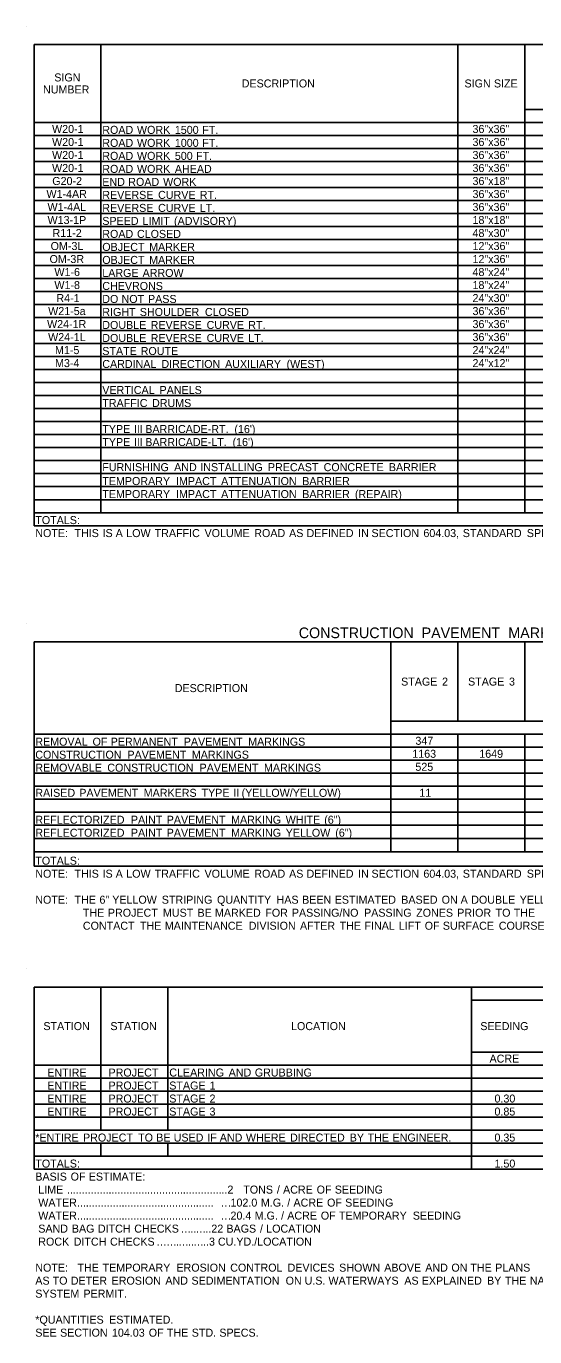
# Model space of a CAD drawing. Extents: x 120 to 5602, y 34 to 1048.
# Drawn here: x 120 to 501, y 66 to 1048 of the extents above; entities that cross this region are included whole.
import ezdxf

# ---------------------------------------------------------------- set-up
doc = ezdxf.new("R2010")
doc.units = 0
doc.layers.add('Default', color=7, linetype='Continuous')
doc.layers.add('STAMP', color=7, linetype='Continuous')

msp = doc.modelspace()

# ---------------------------------------------------------------- linework, layer by layer
at = {"layer": 'Default'}
for p, q in [((125.72, 1034.81), (1233.32, 1034.81)), ((125.72, 674.06), (125.72, 1034.81)), ((125.72, 674.06), (125.72, 1034.81)), ((175.93, 683.81), (175.93, 1034.81)), ((443.57, 683.81), (443.57, 1034.81)), ((493.78, 683.81), (493.78, 1034.81)), ((493.78, 986.06), (644.42, 986.06)), ((125.72, 976.31), (1233.32, 976.31)), ((175.93, 722.81), (175.93, 976.31)), ((443.57, 683.81), (443.57, 976.31)), ((493.78, 683.81), (493.78, 976.31)), ((125.72, 966.56), (1233.32, 966.56)), ((125.72, 956.81), (1233.32, 956.81)), ((125.72, 947.06), (1233.32, 947.06)), ((125.72, 937.31), (1233.32, 937.31)), ((125.72, 927.56), (1233.32, 927.56)), ((125.72, 917.81), (1233.32, 917.81)), ((125.72, 908.06), (1233.32, 908.06)), ((125.72, 898.31), (1233.32, 898.31)), ((125.72, 888.56), (1233.32, 888.56)), ((125.72, 878.81), (1233.32, 878.81)), ((125.72, 869.06), (1233.32, 869.06)), ((125.72, 859.31), (1233.32, 859.31)), ((125.72, 849.56), (1233.32, 849.56)), ((125.72, 839.81), (1233.32, 839.81)), ((125.72, 830.06), (1233.32, 830.06)), ((125.72, 820.31), (1233.32, 820.31)), ((125.72, 810.56), (1233.32, 810.56)), ((125.72, 800.81), (1233.32, 800.81)), ((125.72, 791.06), (1233.32, 791.06)), ((125.72, 781.31), (1233.32, 781.31)), ((125.72, 771.56), (1233.32, 771.56)), ((125.72, 761.81), (1233.32, 761.81)), ((125.72, 752.06), (1233.32, 752.06)), ((125.72, 742.31), (1233.32, 742.31)), ((125.72, 732.56), (1233.32, 732.56)), ((125.72, 722.81), (1233.32, 722.81)), ((125.72, 713.06), (175.93, 713.06)), ((175.93, 713.06), (702.43, 713.06)), ((175.93, 683.81), (175.93, 713.06)), ((125.72, 703.31), (1233.32, 703.31)), ((125.72, 693.56), (1233.32, 693.56)), ((125.72, 683.81), (1233.32, 683.81)), ((125.72, 674.06), (1233.32, 674.06)), ((125.72, 586.92), (969.09, 586.92)), ((125.72, 418.74), (125.72, 586.92)), ((125.72, 418.74), (125.72, 586.92)), ((393.36, 429.46), (393.36, 586.92)), ((443.57, 527.45), (443.57, 586.92)), ((493.78, 527.45), (493.78, 586.92)), ((393.36, 527.45), (969.09, 527.45)), ((393.36, 429.46), (393.36, 527.45)), ((125.72, 517.7), (969.09, 517.7)), ((443.57, 429.46), (443.57, 517.7)), ((443.57, 429.46), (443.57, 517.7)), ((493.78, 429.46), (493.78, 517.7)), ((493.78, 429.46), (493.78, 517.7)), ((125.72, 507.95), (969.09, 507.95)), ((125.72, 498.2), (969.09, 498.2)), ((125.72, 488.45), (969.09, 488.45)), ((125.72, 478.7), (969.09, 478.7)), ((125.72, 468.95), (969.09, 468.95)), ((125.72, 459.2), (969.09, 459.2)), ((125.72, 449.45), (969.09, 449.45)), ((125.72, 439.7), (969.09, 439.7)), ((125.72, 429.46), (969.09, 429.46)), ((125.72, 418.74), (969.09, 418.74)), ((125.72, 328.2), (1244.53, 328.2)), ((125.72, 191.7), (125.72, 328.2)), ((125.72, 191.7), (125.72, 328.2)), ((175.93, 220.95), (175.93, 328.2)), ((226.14, 220.95), (226.14, 328.2)), ((453.81, 191.7), (453.81, 328.2)), ((453.81, 318.45), (1244.53, 318.45)), ((453.81, 279.45), (1118.27, 279.45)), ((125.72, 269.7), (1244.53, 269.7)), ((175.93, 220.95), (175.93, 269.7)), ((226.14, 220.95), (226.14, 269.7)), ((453.81, 220.95), (453.81, 269.7)), ((125.72, 259.95), (1244.53, 259.95)), ((125.72, 250.2), (1244.53, 250.2)), ((125.72, 240.45), (1244.53, 240.45)), ((125.72, 230.7), (1244.53, 230.7)), ((125.72, 220.95), (1244.53, 220.95)), ((125.72, 211.2), (1244.53, 211.2)), ((175.93, 201.45), (175.93, 211.2)), ((175.93, 201.45), (175.93, 211.2)), ((226.14, 201.45), (226.14, 211.2)), ((226.14, 201.45), (226.14, 211.2)), ((453.81, 191.7), (453.81, 211.2)), ((125.72, 201.45), (718.52, 201.45)), ((125.72, 191.7), (1244.53, 191.7))]:
    msp.add_line(p, q, dxfattribs=at)
at = {"layer": 'STAMP'}
for p, q in [((119.87, 1048.46), (119.87, 1048.46)), ((119.87, 600.57), (119.87, 600.57)), ((119.87, 341.85), (119.87, 341.85))]:
    msp.add_line(p, q, dxfattribs=at)

# ---------------------------------------------------------------- texts
at = {"layer": 'Default'}
for s, height, p in [('SIGN', 6, (140.91, 1007.06)), ('NUMBER', 6, (132.45, 998.06)), ('DESCRIPTION', 6, (281.44, 1002.56)), ('SIGN', 6, (448.49, 1002.56)), (' SIZE', 6, (468.31, 1002.56)), ('W20-1', 6, (139.25, 968.43)), ('ROAD', 6, (176.91, 967.76)), (' WORK', 6, (200.68, 967.76)), (' 1500', 6, (229.07, 967.76)), (' FT.', 6, (249.64, 967.76)), ('36"x36"', 6, (454.48, 968.43)), ('W20-1', 6, (139.25, 958.68)), ('ROAD', 6, (176.91, 958.01)), (' WORK', 6, (200.68, 958.01)), (' 1000', 6, (229.07, 958.01)), (' FT.', 6, (249.64, 958.01)), ('36"x36"', 6, (454.48, 958.68)), ('W20-1', 6, (139.25, 948.93)), ('ROAD', 6, (176.91, 948.26)), (' WORK', 6, (200.68, 948.26)), (' 500', 6, (229.07, 948.26)), (' FT.', 6, (244.98, 948.26)), ('36"x36"', 6, (454.48, 948.93)), ('W20-1', 6, (139.25, 939.18)), ('ROAD', 6, (176.91, 938.51)), (' WORK', 6, (200.68, 938.51)), (' AHEAD', 6, (229.07, 938.51)), ('36"x36"', 6, (454.48, 939.18)), ('G20-2', 6, (139.4, 929.43)), ('END', 6, (176.91, 928.76)), (' ROAD', 6, (194.16, 928.76)), (' WORK', 6, (220.26, 928.76)), ('36"x18"', 6, (454.48, 929.43)), ('W1-4AR', 6, (135.05, 919.68)), ('REVERSE', 6, (176.91, 919.01)), (' CURVE', 6, (216.53, 919.01)), (' RT.', 6, (247.76, 919.01)), ('36"x36"', 6, (454.48, 919.68)), ('W1-4AL', 6, (135.84, 909.93)), ('REVERSE', 6, (176.91, 909.26)), (' CURVE', 6, (216.53, 909.26)), (' LT.', 6, (247.76, 909.26)), ('36"x36"', 6, (454.48, 909.93)), ('W13-1P', 6, (135.87, 900.18)), ('SPEED', 6, (176.91, 899.51)), (' LIMIT', 6, (204.88, 899.51)), (' (ADVISORY)', 6, (228.46, 899.51)), ('18"x18"', 6, (454.48, 900.18)), ('R11-2', 6, (139.63, 890.43)), ('ROAD', 6, (176.91, 889.76)), (' CLOSED', 6, (200.68, 889.76)), ('48"x30"', 6, (454.48, 890.43)), ('OM-3L', 6, (138.17, 880.68)), ('OBJECT', 6, (176.91, 880.01)), (' MARKER', 6, (209.81, 880.01)), ('12"x36"', 6, (454.48, 880.68)), ('OM-3R', 6, (137.38, 870.93)), ('OBJECT', 6, (176.91, 870.26)), (' MARKER', 6, (209.81, 870.26)), ('12"x36"', 6, (454.48, 870.93)), ('W1-6', 6, (141, 861.18)), ('LARGE', 6, (176.91, 860.51)), (' ARROW', 6, (204.88, 860.51)), ('48"x24"', 6, (454.48, 861.18)), ('W1-8', 6, (141, 851.43)), ('CHEVRONS', 6, (176.91, 850.76)), ('18"x24"', 6, (454.48, 851.43)), ('R4-1', 6, (142.51, 841.68)), ('DO', 6, (176.91, 841.01)), (' NOT', 6, (189.11, 841.01)), (' PASS', 6, (208.96, 841.01)), ('24"x30"', 6, (454.48, 841.68)), ('W21-5a', 6, (136.33, 831.93)), ('RIGHT', 6, (176.91, 831.26)), (' SHOULDER', 6, (202.82, 831.26)), (' CLOSED', 6, (251.62, 831.26)), ('36"x36"', 6, (454.48, 831.93)), ('W24-1R', 6, (135.51, 822.18)), ('DOUBLE', 6, (176.91, 821.51)), (' REVERSE', 6, (210.94, 821.51)), (' CURVE', 6, (252.89, 821.51)), (' RT.', 6, (284.12, 821.51)), ('36"x36"', 6, (454.48, 822.18)), ('W24-1L', 6, (136.3, 812.43)), ('DOUBLE', 6, (176.91, 811.76)), (' REVERSE', 6, (210.94, 811.76)), (' CURVE', 6, (252.89, 811.76)), (' LT.', 6, (284.12, 811.76)), ('36"x36"', 6, (454.48, 812.43)), ('M1-5', 6, (141.45, 802.68)), ('STATE', 6, (176.91, 802.01)), (' ROUTE', 6, (203.48, 802.01)), ('24"x24"', 6, (454.48, 802.68)), ('M3-4', 6, (141.48, 792.93)), ('CARDINAL', 6, (176.91, 792.26)), (' DIRECTION', 6, (219, 792.26)), (' AUXILIARY', 6, (266.76, 792.26)), (' (WEST)', 6, (312.82, 792.26)), ('24"x12"', 6, (454.48, 792.93)), ('VERTICAL', 6, (176.91, 772.76)), (' PANELS', 6, (217.61, 772.76)), ('TRAFFIC', 6, (176.91, 763.01)), (' DRUMS', 6, (211.97, 763.01)), ('TYPE', 6, (176.91, 743.51)), (' III', 6, (198.36, 743.51)), (' BARRICADE-RT.', 6, (206.92, 743.51)), (" (16')", 6, (273.73, 743.51)), ('TYPE', 6, (176.91, 733.76)), (' III', 6, (198.36, 733.76)), (' BARRICADE-LT.', 6, (206.92, 733.76)), (" (16')", 6, (272.33, 733.76)), ('FURNISHING', 6, (176.91, 714.93)), (' AND', 6, (228.55, 714.93)), (' INSTALLING', 6, (248.13, 714.93)), (' PRECAST', 6, (298.85, 714.93)), (' CONCRETE', 6, (340.61, 714.93)), (' BARRIER', 6, (389.54, 714.93)), ('TEMPORARY', 6, (176.91, 704.51)), (' IMPACT', 6, (229.95, 704.51)), (' ATTENUATION', 6, (263.78, 704.51)), (' BARRIER', 6, (324.58, 704.51)), ('TEMPORARY', 6, (176.91, 694.76)), (' IMPACT', 6, (229.95, 694.76)), (' ATTENUATION', 6, (263.78, 694.76)), (' BARRIER', 6, (324.58, 694.76)), (' (REPAIR)', 6, (364.07, 694.76)), ('TOTALS:', 6, (126.69, 675.26)), ('NOTE:', 6, (126.69, 665.51)), ('  THIS', 6, (151.58, 665.51)), (' IS', 6, (174.89, 665.51)), (' A', 6, (184.7, 665.51)), (' LOW', 6, (192.64, 665.51)), (' TRAFFIC', 6, (213.96, 665.51)), (' VOLUME', 6, (251.35, 665.51)), (' ROAD', 6, (288.64, 665.51)), (' AS', 6, (314.74, 665.51)), (' DEFINED', 6, (327.82, 665.51)), (' IN', 6, (366.5, 665.51)), (' SECTION', 6, (376.52, 665.51)), (' 604.03,', 6, (415.43, 665.51)), (' STANDARD', 6, (444.97, 665.51)), (' SPECIFICATIONS', 6, (492.97, 665.51)), ('CONSTRUCTION', 8, (324.2, 589.75)), (' PAVEMENT', 8, (413.36, 589.75)), (' MARKINGS', 8, (478.35, 589.75)), ('STAGE', 6, (400.94, 554.19)), (' 2', 6, (429.41, 554.19)), ('STAGE', 6, (451.13, 554.19)), (' 3', 6, (479.6, 554.19)), ('DESCRIPTION', 6, (231.22, 549.31)), ('REMOVAL', 6, (126.69, 509.15)), (' OF', 6, (167.39, 509.15)), (' PERMANENT', 6, (180.98, 509.15)), (' PAVEMENT', 6, (235.78, 509.15)), (' MARKINGS', 6, (284.07, 509.15)), ('347', 6, (411.66, 509.82)), ('CONSTRUCTION', 6, (126.69, 499.4)), (' PAVEMENT', 6, (193.54, 499.4)), (' MARKINGS', 6, (241.83, 499.4)), ('1163', 6, (409.33, 500.07)), ('1649', 6, (459.54, 500.07)), ('REMOVABLE', 6, (126.69, 489.65)), (' CONSTRUCTION', 6, (178.43, 489.65)), (' PAVEMENT', 6, (247.61, 489.65)), (' MARKINGS', 6, (295.89, 489.65)), ('525', 6, (411.64, 490.32)), ('RAISED', 6, (126.69, 470.82)), (' PAVEMENT', 6, (157.46, 470.82)), (' MARKERS', 6, (205.75, 470.82)), (' TYPE', 6, (249.1, 470.82)), (' II', 6, (272.88, 470.82)), (' (YELLOW/YELLOW)', 6, (279.11, 470.82)), ('11', 6, (414.57, 470.82)), ('REFLECTORIZED', 6, (126.69, 450.65)), (' PAINT', 6, (196.12, 450.65)), (' PAVEMENT', 6, (222.97, 450.65)), (' MARKING', 6, (271.25, 450.65)), (' WHITE', 6, (312.18, 450.65)), (' (6")', 6, (341.07, 450.65)), ('REFLECTORIZED', 6, (126.69, 440.9)), (' PAINT', 6, (196.12, 440.9)), (' PAVEMENT', 6, (222.97, 440.9)), (' MARKING', 6, (271.25, 440.9)), (' YELLOW', 6, (312.18, 440.9)), (' (6")', 6, (349.35, 440.9)), ('TOTALS:', 6, (126.69, 419.94)), ('NOTE:', 6, (126.69, 410.19)), ('  THIS', 6, (151.58, 410.19)), (' IS', 6, (174.89, 410.19)), (' A', 6, (184.7, 410.19)), (' LOW', 6, (192.64, 410.19)), (' TRAFFIC', 6, (213.96, 410.19)), (' VOLUME', 6, (251.35, 410.19)), (' ROAD', 6, (288.64, 410.19)), (' AS', 6, (314.74, 410.19)), (' DEFINED', 6, (327.82, 410.19)), (' IN', 6, (366.5, 410.19)), (' SECTION', 6, (376.52, 410.19)), (' 604.03,', 6, (415.43, 410.19)), (' STANDARD', 6, (444.97, 410.19)), (' SPECIFICATIONS', 6, (492.97, 410.19)), ('NOTE:', 6, (126.69, 390.69)), ('  THE', 6, (151.58, 390.69)), (' 6"', 6, (172.56, 390.69)), (' YELLOW', 6, (182.13, 390.69)), (' STRIPING', 6, (219.3, 390.69)), (' QUANTITY', 6, (260.7, 390.69)), (' HAS', 6, (305.35, 390.69)), (' BEEN', 6, (324.48, 390.69)), (' ESTIMATED', 6, (348.95, 390.69)), (' BASED', 6, (398.82, 390.69)), (' ON', 6, (429.12, 390.69)), (' A', 6, (443.34, 390.69)), (' DOUBLE', 6, (451.27, 390.69)), (' YELLOW', 6, (487.63, 390.69)), ('  THE', 6, (157.89, 380.94)), (' PROJECT', 6, (178.87, 380.94)), (' MUST', 6, (220.16, 380.94)), (' BE', 6, (246.07, 380.94)), (' MARKED', 6, (259.14, 380.94)), (' FOR', 6, (296.89, 380.94)), (' PASSING/NO', 6, (316.8, 380.94)), (' PASSING', 6, (370.93, 380.94)), (' ZONES', 6, (410.01, 380.94)), (' PRIOR', 6, (440.79, 380.94)), (' TO', 6, (469.55, 380.94)), (' THE', 6, (483.15, 380.94)), ('  CONTACT', 6, (157.89, 371.19)), (' THE', 6, (202.9, 371.19)), (' MAINTENANCE', 6, (221.55, 371.19)), (' DIVISION', 6, (284.46, 371.19)), (' AFTER', 6, (322.9, 371.19)), (' THE', 6, (352.6, 371.19)), (' FINAL', 6, (371.25, 371.19)), (' LIFT', 6, (397.03, 371.19)), (' OF', 6, (416.42, 371.19)), (' SURFACE', 6, (430.01, 371.19)), (' COURSE', 6, (471.96, 371.19)), ('STATION', 6, (132.76, 295.95)), ('STATION', 6, (182.98, 295.95)), ('LOCATION', 6, (318.42, 295.95)), ('SEEDING', 6, (460.3, 295.95)), ('ACRE', 6, (467.24, 271.58)), ('ENTIRE', 6, (135.68, 261.15)), ('PROJECT', 6, (181.56, 261.15)), ('CLEARING', 6, (227.12, 261.15)), (' AND', 6, (269.45, 261.15)), (' GRUBBING', 6, (289.03, 261.15)), ('ENTIRE', 6, (135.68, 251.4)), ('PROJECT', 6, (181.56, 251.4)), ('STAGE', 6, (227.12, 251.4)), (' 1', 6, (255.09, 251.4)), ('ENTIRE', 6, (135.68, 241.65)), ('PROJECT', 6, (181.56, 241.65)), ('STAGE', 6, (227.12, 241.65)), (' 2', 6, (255.09, 241.65)), ('0.30', 6, (470.96, 241.65)), ('ENTIRE', 6, (135.68, 231.9)), ('PROJECT', 6, (181.56, 231.9)), ('STAGE', 6, (227.12, 231.9)), (' 3', 6, (255.09, 231.9)), ('0.85', 6, (470.93, 231.9)), ('*ENTIRE', 6, (126.69, 212.4)), (' PROJECT', 6, (160.25, 212.4)), (' TO', 6, (201.54, 212.4)), (' BE', 6, (215.14, 212.4)), (' USED', 6, (228.2, 212.4)), (' IF', 6, (253.38, 212.4)), (' AND', 6, (262.77, 212.4)), (' WHERE', 6, (282.36, 212.4)), (' DIRECTED', 6, (315.44, 212.4)), (' BY', 6, (360.18, 212.4)), (' THE', 6, (373.63, 212.4)), (' ENGINEER.', 6, (392.28, 212.4)), ('0.35', 6, (470.93, 212.4)), ('TOTALS:', 6, (126.69, 192.9)), ('1.50', 6, (470.96, 192.9)), ('BASIS', 6, (126.69, 183.15)), (' OF', 6, (150.95, 183.15)), (' ESTIMATE:', 6, (164.54, 183.15)), (' LIME', 6, (126.69, 173.4)), (' ......................................................2', 6, (148.14, 173.4)), (' TONS', 6, (280.38, 173.4)), (' /', 6, (305.56, 173.4)), (' ACRE', 6, (310.22, 173.4)), (' OF', 6, (335.39, 173.4)), (' SEEDING', 6, (348.98, 173.4)), (' WATER..............................................', 6, (126.69, 163.65)), ('102.0', 6, (273.04, 163.65)), (' M.G.', 6, (293.61, 163.65)), (' /', 6, (313.36, 163.65)), (' ACRE', 6, (318.02, 163.65)), (' OF', 6, (343.2, 163.65)), (' SEEDING', 6, (356.78, 163.65)), (' WATER..............................................', 6, (126.69, 153.9)), ('…', 6, (265.64, 163.65)), ('20.4', 6, (273.04, 153.9)), (' M.G.', 6, (288.94, 153.9)), (' /', 6, (308.7, 153.9)), (' ACRE', 6, (313.36, 153.9)), (' OF', 6, (338.53, 153.9)), (' TEMPORARY', 6, (352.12, 153.9)), (' SEEDING', 6, (407.49, 153.9)), (' SAND', 6, (126.69, 144.15)), (' BAG', 6, (151.87, 144.15)), (' DITCH', 6, (171.38, 144.15)), (' CHECKS', 6, (198.64, 144.15)), ('..22', 6, (254.2, 144.15)), ('…', 6, (265.64, 153.9)), (' BAGS', 6, (267.73, 144.15)), (' /', 6, (292.92, 144.15)), (' LOCATION', 6, (297.58, 144.15)), (' ROCK', 6, (126.69, 134.4)), (' DITCH', 6, (153.23, 134.4)), (' CHECKS', 6, (180.49, 134.4)), ('…', 6, (235.48, 144.15)), ('..', 6, (242.88, 144.15)), ('…', 6, (246.8, 144.15)), ('..3', 6, (252.44, 134.4)), (' CU.YD./LOCATION', 6, (261.38, 134.4)), ('…', 6, (217.32, 134.4)), ('…', 6, (224.72, 134.4)), ('.', 6, (232.12, 134.4)), ('…', 6, (233.72, 134.4)), ('..', 6, (241.12, 134.4)), ('…', 6, (245.04, 134.4)), ('NOTE:', 6, (126.69, 114.9)), ('   THE', 6, (151.58, 114.9)), (' TEMPORARY', 6, (174.89, 114.9)), (' EROSION', 6, (230.26, 114.9)), (' CONTROL', 6, (270.57, 114.9)), (' DEVICES', 6, (313.59, 114.9)), (' SHOWN', 6, (352.28, 114.9)), (' ABOVE', 6, (386.06, 114.9)), (' AND', 6, (416.83, 114.9)), (' ON', 6, (436.42, 114.9)), (' THE', 6, (450.63, 114.9)), (' PLANS', 6, (469.28, 114.9)), ('AS', 6, (126.69, 105.15)), (' TO', 6, (137.44, 105.15)), (' DETER', 6, (151.04, 105.15)), (' EROSION', 6, (181.67, 105.15)), (' AND', 6, (221.98, 105.15)), (' SEDIMENTATION', 6, (241.56, 105.15)), (' ON', 6, (312.14, 105.15)), (' U.S.', 6, (326.36, 105.15)), (' WATERWAYS', 6, (344.26, 105.15)), (' AS', 6, (401.11, 105.15)), (' EXPLAINED', 6, (414.19, 105.15)), (' BY', 6, (463.13, 105.15)), (' THE', 6, (476.58, 105.15)), (' NATIONAL', 6, (495.23, 105.15)), ('SYSTEM', 6, (126.69, 95.4)), (' PERMIT.', 6, (160.54, 95.4)), ('*QUANTITIES', 6, (126.69, 75.9)), (' ESTIMATED.', 6, (179.82, 75.9)), ('SEE', 6, (126.69, 66.15)), (' SECTION', 6, (143.02, 66.15)), (' 104.03', 6, (181.93, 66.15)), (' OF', 6, (209.51, 66.15)), (' THE', 6, (223.1, 66.15)), (' STD.', 6, (241.75, 66.15)), (' SPECS.', 6, (262.44, 66.15))]:
    msp.add_text(s, height=height, dxfattribs=at).set_placement(p)

doc.saveas('drawing.dxf')
